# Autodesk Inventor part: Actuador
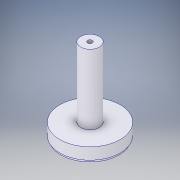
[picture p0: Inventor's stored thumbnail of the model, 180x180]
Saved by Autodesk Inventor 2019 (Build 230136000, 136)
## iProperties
Created: 2019-04
Part Number: Actuador
Material: Generic
Document SubType Name: Modeling
Designer: Plo
Density: 1 g/cm^3
Appearance: Cool White
Author: Plo
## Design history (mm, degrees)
sketch "Sketch1"
  geometry: C1 r 13 at (0, 0); 1 further point
  constraints: 1 centre point, 1 coincident
  dimensions: "d0" = 26 diameter of C1
extrude "Extrusion1" new body sketch "Sketch1" distance "d1" = 6; taper "d2" = 0 deg
sketch "Sketch2"
  geometry: C1 r 12.5 at (0, 0); C2 r 13 at (0, 0) reference; 1 further point
  constraints: 1 centre point, 1 coincident
  dimensions: "d3" = 25 diameter of C1
extrude "Extrusion2" cut sketch "Sketch2" distance "d4" = 1; taper "d5" = 0 deg
sketch "Sketch3"
  geometry: C1 r 12.25 at (0, 0); 1 further point
  constraints: 1 centre point, 1 coincident
  dimensions: "d6" = 24.5 diameter of C1
extrude "Extrusion3" cut sketch "Sketch3" distance "d7" = 5; taper "d8" = 0 deg
sketch "Sketch4"
  geometry: C1 r 4 at (0, 0); 1 further point
  constraints: 1 centre point, 1 coincident
  dimensions: "d9" = 8 diameter of C1
extrude "Extrusion4" join sketch "Sketch4" distance "d10" = 30; taper "d11" = 0 deg
sketch "Sketch5"
  geometry: C1 r 4 at (0, 0) reference; C2 r 1 at (0, 0); 1 further point
  constraints: 1 centre point, 1 coincident
  dimensions: "d12" = 2 diameter of C2
extrude "Extrusion5" cut sketch "Sketch5" distance "d13" = 2; taper "d14" = 0 deg
sketch "Sketch6"
  geometry: C1 r 3 at (0, 0); 1 further point
  constraints: 1 centre point, 1 coincident
  dimensions: "d15" = 6 diameter of C1
extrude "Extrusion6" cut sketch "Sketch6" distance "d16" = 28; taper "d17" = 0 deg
body "Solid1"
